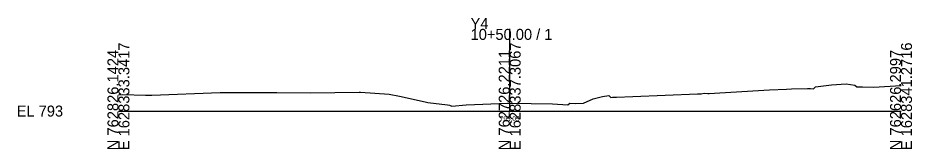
# Model space of a CAD drawing. Extents: x -26 to 203, y -10 to 3017.
# Drawn here: x -25.7 to 202.8, y 990.3 to 1023.7 of the extents above; entities that cross this region are included whole.
import ezdxf

# ---------------------------------------------------------------- set-up
doc = ezdxf.new("R2010")
doc.units = 0
for name, color, linetype in [('Default', 7, 'Continuous'), ('Exist Cross Section Cell', 7, 'Continuous'), ('Exist XS Center Line Elevation Label', 7, 'Continuous'), ('Exist XS Ground Line', 7, 'Continuous')]:
    doc.layers.add(name, color=color, linetype=linetype)

msp = doc.modelspace()

# ---------------------------------------------------------------- linework, layer by layer
at = {"layer": 'Exist Cross Section Cell'}
for p, q in [((100, 1000), (100, 1020.94)), ((0, 1000), (100, 1000)), ((100, 1000), (200, 1000))]:
    msp.add_line(p, q, dxfattribs=at)
at = {"layer": 'Exist XS Ground Line'}
msp.add_lwpolyline([(0, 1004.17), (1.04, 1004.23), (6.94, 1004.06), (7.72, 1004.03), (8.12, 1004.04), (8.56, 1004.06), (25.97, 1004.74), (40.45, 1004.73), (49.11, 1004.66), (61.55, 1004.8), (61.86, 1004.8), (69.22, 1004.3), (71.87, 1003.83), (78.41, 1002.36), (79.09, 1002.21), (84.13, 1001.62), (84.58, 1001.54), (85.23, 1001.26), (88.87, 1001.56), (99.4, 1002.04), (99.72, 1002.05), (100.07, 1002.05), (110.93, 1001.84), (114.82, 1001.6), (115.34, 1001.99), (116.8, 1001.96), (118.84, 1002.01), (121.34, 1003.15), (123.69, 1003.7), (125.31, 1003.99), (125.81, 1003.49), (126.3, 1003.52), (127.31, 1003.57), (131.44, 1003.69), (148.01, 1004.37), (148.97, 1004.39), (149.71, 1004.53), (150.64, 1004.47), (150.97, 1004.5), (153.68, 1004.64), (166.39, 1005.42), (170.72, 1005.61), (172.05, 1005.65), (176.14, 1005.77), (176.88, 1005.73), (177.65, 1005.69), (178.15, 1006.19), (182.23, 1006.66), (186.01, 1006.98), (188.19, 1006.64), (188.69, 1006.14), (189.47, 1006.18), (190.19, 1006.21), (193, 1006.12), (200, 1006.5)], dxfattribs=at)

# ---------------------------------------------------------------- texts
at = {"layer": 'Default'}
msp.add_text('-', height=0.0001, dxfattribs=at).set_placement((0, 1000))
at = {"layer": 'Exist Cross Section Cell'}
for s, p in [('Y4', (90, 1020.94)), ('10+50.00 / 1', (90, 1018.14)), ('EL 793', (-26, 998.6))]:
    msp.add_text(s, height=2.8, dxfattribs=at).set_placement(p)
for s, p in [('E 1628333.3417', (2.8, 990)), ('E 1628337.3067', (102.8, 990)), ('E 1628341.2716', (202.8, 990)), ('N 762826.1424', (0, 990)), ('N 762726.2211', (100, 990)), ('N 762626.2997', (200, 990))]:
    msp.add_text(s, height=2.8, rotation=90, dxfattribs=at).set_placement(p)
at = {"layer": 'Exist XS Center Line Elevation Label'}
msp.add_text('795.05', height=1.2, dxfattribs=at).set_placement((97.44, 997.45))

doc.saveas('drawing.dxf')
